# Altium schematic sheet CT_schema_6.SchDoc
size 184 x 159 mm
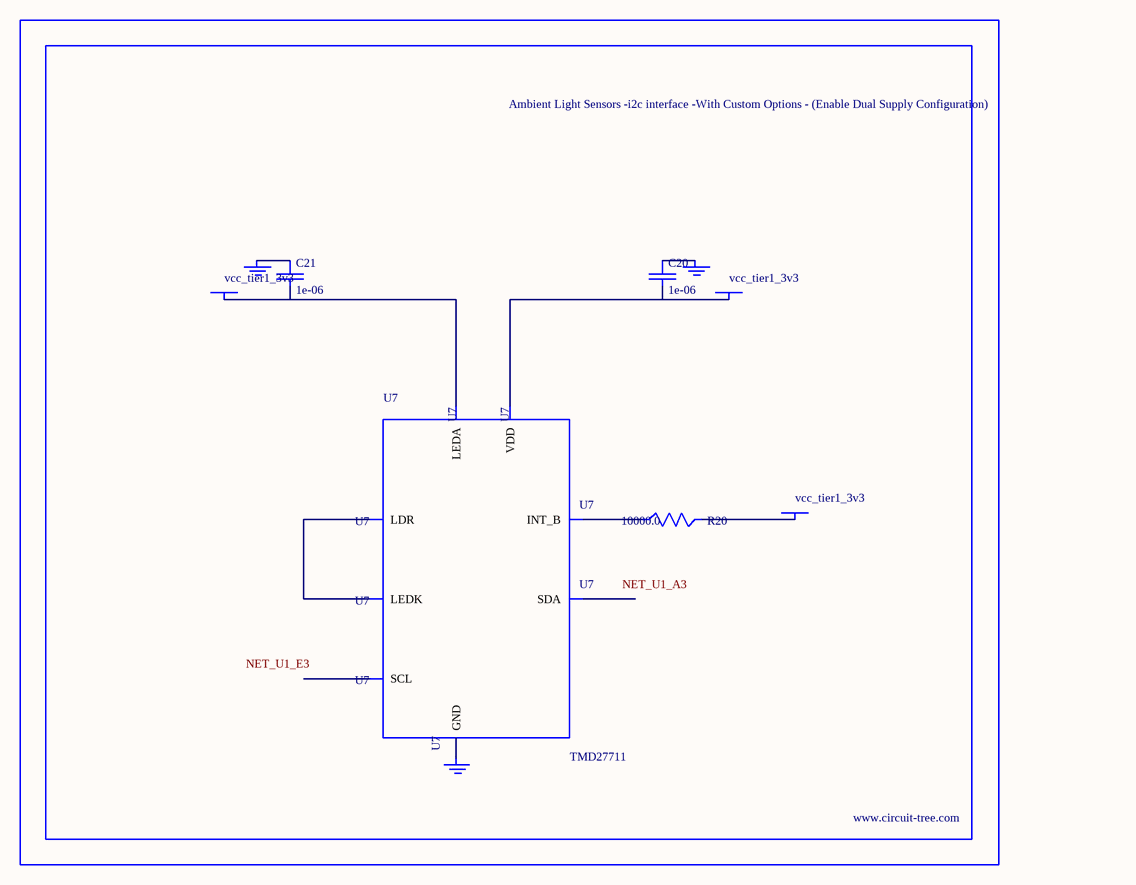
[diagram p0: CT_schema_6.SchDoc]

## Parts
BORDER5  (no value)
C20  1e-06  [C0603]
C21  1e-06  [C0603]
GND_INSTANCE_5_0  (no value)
GND_INSTANCE_5_1  (no value)
GND_INSTANCE_5_2  (no value)
POWER_INSTANCE_5_0  vcc_tier1_3v3
POWER_INSTANCE_5_1  vcc_tier1_3v3
POWER_INSTANCE_5_2  vcc_tier1_3v3
R20  10000.0  [R0603]
U7  TMD27711  [SMD-8]

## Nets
NetC20_1: C20.1 GND_INSTANCE_5_0.0(GND)
NetC20_2: C20.2 POWER_INSTANCE_5_0.0(PWR) U7.1(VDD)
NetC21_1: C21.1 GND_INSTANCE_5_1.0(GND)
NetC21_2: C21.2 POWER_INSTANCE_5_1.0(PWR) U7.4(LEDA)
NetGND_INSTANCE_5_2_0: GND_INSTANCE_5_2.0(GND) U7.3(GND)
NetPOWER_INSTANCE_5_2_0: POWER_INSTANCE_5_2.0(PWR) R20.2
NetR20_1: R20.1 U7.7(INT_B)
NetU7_5: U7.5(LEDK) U7.6(LDR)

Not connected (* = marked no-connect by the designer): U7 2(SCL) 8(SDA)

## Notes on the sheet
- Labels drawn without touching a wire or pin: NET_U1_A3, NET_U1_E3

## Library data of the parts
BORDER5 = BORDER_PAGE5
C20 C21 = C0603C105K3RACTU
GND_INSTANCE_5_0-GND_INSTANCE_5_2 = GND
POWER_INSTANCE_5_0-POWER_INSTANCE_5_2 = PWR
R20 = RC0603JR-0710KL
